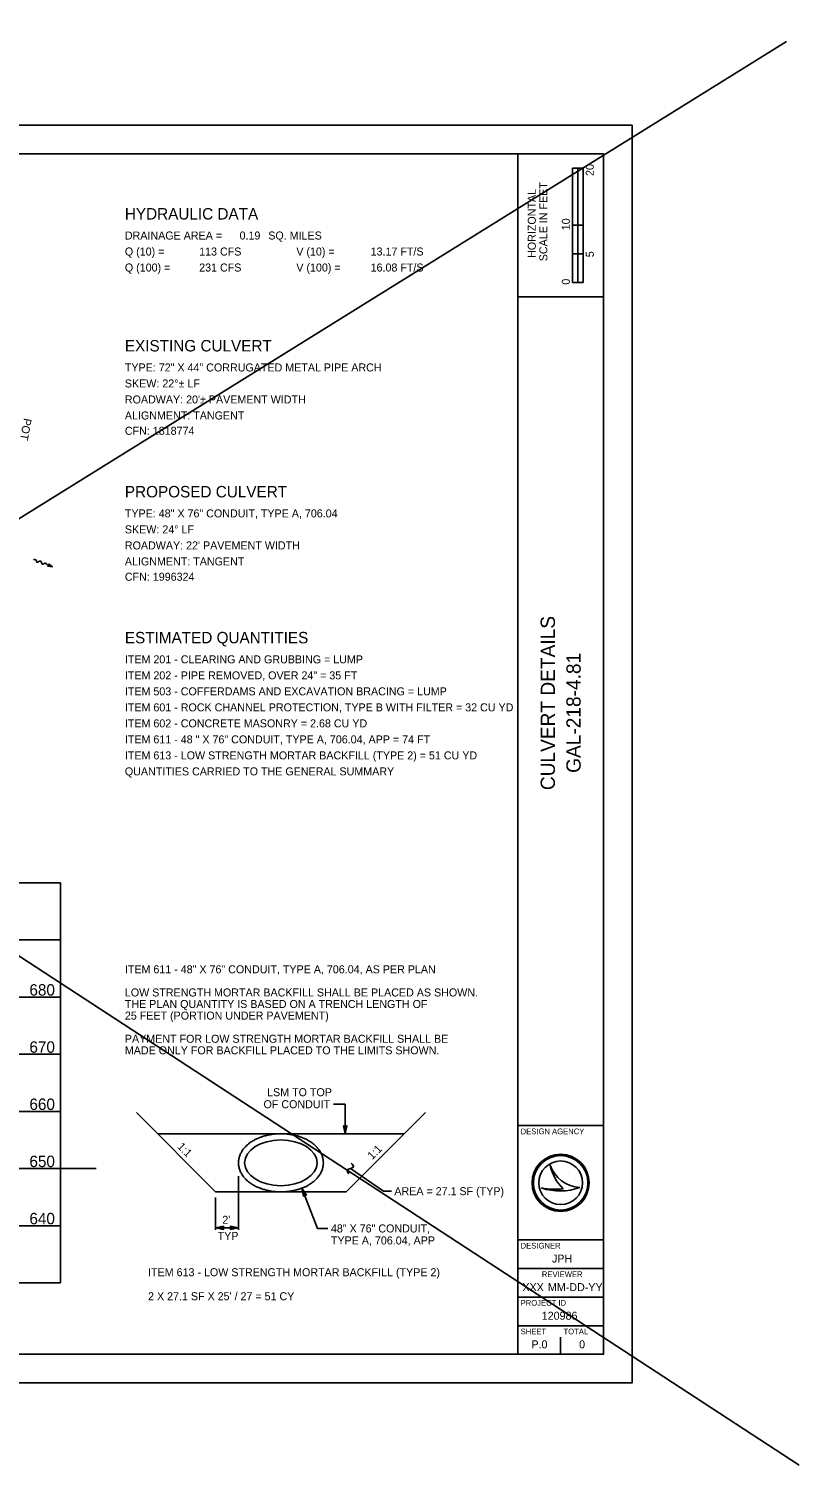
# Model space of a CAD drawing. Extents: x -1270 to 3371, y -118 to 220.
# Drawn here: x -1010.8 to -876, y -117.6 to 133.7 of the extents above; entities that cross this region are included whole.
import ezdxf

# ---------------------------------------------------------------- set-up
doc = ezdxf.new("R2010")
doc.units = 0
for name, color, linetype in [('_CIVIL_CONSTRUCTION', 7, 'Continuous'), ('Default', 7, 'Continuous'), ('DR_P_Culvert', 7, 'Continuous'), ('DR_X_Culvert', 7, 'Continuous'), ('GE_P_Alignment', 7, 'Continuous'), ('GE_P_Alignment_100_Distances', 7, 'Continuous'), ('PF_P_Grade_Line', 7, 'Continuous'), ('PF_X_Ground_Line', 7, 'Continuous'), ('SC_Scratch1', 7, 'Continuous'), ('TX_P_1', 7, 'Continuous'), ('TX_X_1', 7, 'Continuous')]:
    doc.layers.add(name, color=color, linetype=linetype)

msp = doc.modelspace()

# ---------------------------------------------------------------- linework, layer by layer
at = {"layer": '_CIVIL_CONSTRUCTION'}
for points in [[(-955.76, -58.24), (-955.2, -58.24), (-955.48, -59.64)], [(-962.25, -70.35), (-962.77, -70.55), (-963.02, -69.14)], [(-976.73, -75.81), (-976.73, -76.37), (-978.13, -76.09)], [(-975.53, -76.37), (-975.53, -75.81), (-974.13, -76.09)]]:
    msp.add_lwpolyline(points, close=True, dxfattribs=at)
at = {"layer": 'Default'}
msp.add_line((-1215.28, -65.72), (-999.03, -65.72), dxfattribs=at)
at = {"layer": 'DR_X_Culvert'}
msp.add_lwpolyline([(-1245.26, -103.22), (-905.26, -103.22), (-905.26, 116.78), (-1245.26, 116.78)], close=True, dxfattribs=at)
at = {"layer": 'GE_P_Alignment_100_Distances'}
for p, q in [((-1007.53, 39.64), (-1006.7, 39.55)), ((-1006.7, 39.55), (-1007.38, 40.04))]:
    msp.add_line(p, q, dxfattribs=at)
msp.add_spline([(-1006.7, 39.55), (-1007.48, 39.85), (-1007.76, 40.04), (-1007.93, 40.18), (-1008.46, 39.99), (-1008.76, 40.55), (-1009.43, 40.36), (-1009.46, 40.61), (-1009.97, 40.8)], degree=3, dxfattribs=at)
at = {"layer": 'PF_P_Grade_Line'}
for p, q in [((-978.13, -69.8), (-991.99, -55.94)), ((-955.28, -69.8), (-941.42, -55.94)), ((-945.12, -59.64), (-988.3, -59.64)), ((-955.28, -69.8), (-978.13, -69.8))]:
    msp.add_line(p, q, dxfattribs=at)
msp.add_ellipse((-966.71, -64.72), major_axis=(6.34, 0), ratio=0.630915, dxfattribs=at)
msp.add_open_spline([(-959.28, -64.72), (-959.28, -64.53), (-959.3, -64.34), (-959.36, -63.97), (-959.4, -63.79), (-959.51, -63.43), (-959.58, -63.25), (-959.75, -62.92), (-959.84, -62.75), (-960.05, -62.43), (-960.16, -62.28), (-960.41, -61.99), (-960.54, -61.85), (-960.97, -61.44), (-961.29, -61.2), (-962, -60.75), (-962.37, -60.56), (-963.16, -60.23), (-963.58, -60.09), (-964.43, -59.86), (-964.88, -59.78), (-965.78, -59.66), (-966.24, -59.64), (-967.17, -59.64), (-967.63, -59.66), (-968.54, -59.78), (-968.98, -59.86), (-969.84, -60.09), (-970.25, -60.23), (-971.04, -60.56), (-971.42, -60.75), (-972.12, -61.2), (-972.44, -61.44), (-972.87, -61.85), (-973, -61.99), (-973.25, -62.28), (-973.37, -62.43), (-973.57, -62.75), (-973.67, -62.92), (-973.83, -63.25), (-973.9, -63.43), (-974.01, -63.79), (-974.06, -63.97), (-974.12, -64.34), (-974.13, -64.53), (-974.13, -64.91), (-974.12, -65.1), (-974.06, -65.47), (-974.01, -65.65), (-973.9, -66.01), (-973.83, -66.18), (-973.67, -66.52), (-973.57, -66.69), (-973.37, -67), (-973.25, -67.15), (-973, -67.45), (-972.87, -67.59), (-972.44, -67.99), (-972.12, -68.24), (-971.42, -68.69), (-971.04, -68.88), (-970.25, -69.21), (-969.84, -69.35), (-968.98, -69.57), (-968.54, -69.66), (-967.63, -69.77), (-967.17, -69.8), (-966.24, -69.8), (-965.78, -69.77), (-964.88, -69.66), (-964.43, -69.57), (-963.58, -69.35), (-963.16, -69.21), (-962.37, -68.88), (-962, -68.69), (-961.29, -68.24), (-960.97, -67.99), (-960.54, -67.59), (-960.41, -67.45), (-960.16, -67.15), (-960.05, -67), (-959.84, -66.69), (-959.75, -66.52), (-959.58, -66.18), (-959.51, -66.01), (-959.4, -65.65), (-959.36, -65.47), (-959.3, -65.1), (-959.28, -64.91), (-959.28, -64.72)], degree=3, dxfattribs=at)
at = {"layer": 'PF_X_Ground_Line'}
for p, q in [((-1225.28, -25.72), (-1005.28, -25.72)), ((-1225.28, -35.72), (-1005.28, -35.72)), ((-1225.28, -45.72), (-1005.28, -45.72)), ((-1225.28, -55.72), (-1005.28, -55.72)), ((-1225.28, -65.72), (-1005.28, -65.72)), ((-1225.28, -75.72), (-1005.28, -75.72))]:
    msp.add_line(p, q, dxfattribs=at)
at = {"layer": 'SC_Scratch1'}
for p, q in [((-915.7, 89.28), (-915.7, 109.28)), ((-913.82, 109.28), (-915.7, 109.28)), ((-915.7, 99.28), (-915.7, 109.28)), ((-915.7, 109.28), (-914.76, 109.28)), ((-914.76, 109.28), (-914.76, 99.28)), ((-914.76, 109.28), (-914.76, 109.28)), ((-913.82, 109.28), (-913.82, 89.28)), ((-914.76, 99.28), (-915.7, 99.28)), ((-913.83, 99.28), (-914.76, 99.28)), ((-914.76, 99.28), (-914.76, 94.28)), ((-913.83, 94.28), (-913.83, 99.28)), ((-914.76, 94.28), (-915.7, 94.28)), ((-915.7, 94.28), (-915.7, 89.28)), ((-914.76, 89.28), (-914.76, 94.28)), ((-914.76, 94.28), (-913.83, 94.28)), ((-913.82, 89.28), (-915.7, 89.28)), ((-915.7, 89.28), (-914.76, 89.28)), ((-1005.28, -15.72), (-1225.28, -15.72)), ((-1005.28, -85.72), (-1005.28, -15.72)), ((-919.59, -65.12), (-919.59, -65.12)), ((-921.09, -69.12), (-921.09, -69.12)), ((-917.76, -68.22), (-917.76, -68.22)), ((-914.39, -69.03), (-914.39, -69.03)), ((-1225.28, -85.72), (-1005.28, -85.72)), ((-917.76, -98.22), (-917.76, -95.22)), ((-921.51, -96.47), (-921.51, -96.47))]:
    msp.add_line(p, q, dxfattribs=at)
for radius in [5, 4.77, 4.77, 3.82]:
    msp.add_circle((-917.76, -68.22), radius, dxfattribs=at)
for centre, radius, start, end in [((-914.1, -63.24), 5.8, 198.9257, 198.9319), ((-911.8, -63.52), 7.96, 191.6379, 191.6421), ((-914.1, -63.24), 5.8, 198.9319, 267.1657), ((-911.8, -63.52), 7.96, 191.6421, 226.0947), ((-917.87, -59.52), 10.13, 251.4576, 290.0832), ((-918.78, -56.68), 12.66, 259.4964, 259.4995), ((-917.87, -59.52), 10.13, 251.4527, 251.4576), ((-918.78, -56.68), 12.66, 259.4995, 276.6672)]:
    msp.add_arc(centre, radius, start, end, dxfattribs=at)
at = {"layer": 'TX_P_1'}
for p, q in [((-1261.12, 133.66), (-876.01, -117.63)), ((-878.22, 131.45), (-1269.59, -111.73)), ((-955.48, -54.47), (-957.53, -54.47)), ((-955.48, -59.64), (-955.48, -54.47)), ((-974.13, -67.05), (-974.13, -76.45)), ((-948.77, -69.68), (-954.55, -65.69)), ((-963.02, -69.14), (-960.3, -76.2)), ((-947.37, -69.68), (-948.77, -69.68)), ((-978.13, -70.78), (-978.13, -76.45)), ((-978.13, -76.09), (-974.13, -76.09)), ((-960.3, -76.2), (-958.49, -76.2))]:
    msp.add_line(p, q, dxfattribs=at)
msp.add_spline([(-954.83, -66.66), (-955.1, -65.97), (-954.03, -65.43), (-954.42, -64.78)], degree=3, dxfattribs=at)
at = {"layer": 'TX_X_1'}
for p, q in [((-925.26, -98.22), (-925.26, 111.78)), ((-925.26, 86.78), (-910.26, 86.78)), ((-925.26, -58.22), (-910.26, -58.22)), ((-925.26, -78.22), (-910.26, -78.22)), ((-925.26, -83.22), (-910.26, -83.22)), ((-925.26, -88.22), (-910.26, -88.22)), ((-925.26, -93.22), (-910.26, -93.22))]:
    msp.add_line(p, q, dxfattribs=at)
msp.add_lwpolyline([(-1230.26, 111.78), (-910.26, 111.78), (-910.26, -98.22), (-1230.26, -98.22)], close=True, dxfattribs=at)

# ---------------------------------------------------------------- texts
at = {"layer": 'DR_P_Culvert'}
msp.add_text('POT', height=1.4, rotation=259.759, dxfattribs=at).set_placement((-1011.69, 65.6))
at = {"layer": 'GE_P_Alignment'}
for s, p in [('ITEM 611 - 48" X 76" CONDUIT, TYPE A, 706.04, AS PER PLAN', (-994.01, -31.57)), ('LOW STRENGTH MORTAR BACKFILL SHALL BE PLACED AS SHOWN.', (-994.01, -35.62)), ('THE PLAN QUANTITY IS BASED ON A TRENCH LENGTH OF ', (-994.01, -37.64)), ('25 FEET (PORTION UNDER PAVEMENT)', (-994.01, -39.67)), ('PAYMENT FOR LOW STRENGTH MORTAR BACKFILL SHALL BE', (-994.01, -43.72)), ('MADE ONLY FOR BACKFILL PLACED TO THE LIMITS SHOWN.', (-994.01, -45.74))]:
    msp.add_text(s, height=1.4, dxfattribs=at).set_placement(p)
at = {"layer": 'SC_Scratch1'}
for s, height, p in [('20', 1.4, (-911.96, 107.91)), ('HORIZONTAL', 1.4, (-922.11, 93.57)), ('SCALE IN FEET', 1.4, (-920.09, 92.99)), ('10', 1.4, (-916.16, 98.41)), ('5', 1.4, (-911.96, 93.69)), ('0', 1.4, (-916.16, 88.89)), ('CULVERT DETAILS', 2.5, (-918.76, 0.47)), ('GAL-218-4.81', 2.5, (-914.26, 3.49))]:
    msp.add_text(s, height=height, rotation=90, dxfattribs=at).set_placement(p)
for s, height, p in [('HYDRAULIC DATA', 2, (-994.01, 100.29)), ('DRAINAGE AREA =', 1.4, (-994.01, 96.79)), ('0.19', 1.4, (-973.94, 96.79)), ('SQ. MILES', 1.4, (-968.92, 96.79)), ('Q (10) =', 1.4, (-994.01, 93.99)), ('113 CFS', 1.4, (-981.01, 93.99)), ('V (10) =', 1.4, (-964.01, 93.99)), ('13.17 FT/S', 1.4, (-951.01, 93.99)), ('Q (100) =', 1.4, (-994.01, 91.19)), ('231 CFS', 1.4, (-981.01, 91.19)), ('V (100) =', 1.4, (-964.01, 91.19)), ('16.08 FT/S', 1.4, (-951.01, 91.19)), ('EXISTING CULVERT', 2, (-994.01, 77.21)), ('TYPE: 72" X 44" CORRUGATED METAL PIPE ARCH', 1.4, (-994.01, 73.71)), ('SKEW: 22°± LF', 1.4, (-994.01, 70.91)), ("ROADWAY: 20'± PAVEMENT WIDTH", 1.4, (-994.01, 68.11)), ('ALIGNMENT: TANGENT', 1.4, (-994.01, 65.31)), ('CFN: 1818774', 1.4, (-994.01, 62.63)), ('PROPOSED CULVERT', 2, (-994.01, 51.68)), ('TYPE: 48" X 76" CONDUIT, TYPE A, 706.04', 1.4, (-994.01, 48.18)), ('SKEW: 24° LF', 1.4, (-994.01, 45.38)), ("ROADWAY: 22' PAVEMENT WIDTH", 1.4, (-994.01, 42.58)), ('ALIGNMENT: TANGENT', 1.4, (-994.01, 39.78)), ('CFN: 1996324', 1.4, (-994.01, 37.1)), ('ESTIMATED QUANTITIES', 2, (-994.01, 26.15)), ('ITEM 201 - CLEARING AND GRUBBING = LUMP', 1.4, (-994.01, 22.65)), ('ITEM 202 - PIPE REMOVED, OVER 24" = 35 FT', 1.4, (-994.01, 19.85)), ('ITEM 503 - COFFERDAMS AND EXCAVATION BRACING = LUMP', 1.4, (-994.01, 17.05)), ('ITEM 601 - ROCK CHANNEL PROTECTION, TYPE B WITH FILTER = 32 CU YD', 1.4, (-994.01, 14.25)), ('ITEM 602 - CONCRETE MASONRY = 2.68 CU YD', 1.4, (-994.01, 11.45)), ('ITEM 611 - 48 " X 76" CONDUIT, TYPE A, 706.04, APP = 74 FT', 1.4, (-994.01, 8.65)), ('ITEM 613 - LOW STRENGTH MORTAR BACKFILL (TYPE 2) = 51 CU YD', 1.4, (-994.01, 5.85)), ('QUANTITIES CARRIED TO THE GENERAL SUMMARY', 1.4, (-994.01, 3.05)), ('680', 2, (-1010.71, -35.47)), ('670', 2, (-1010.71, -45.47)), ('660', 2, (-1010.71, -55.47)), ('DESIGN AGENCY', 1, (-924.76, -59.72)), ('650', 2, (-1010.71, -65.47)), ('640', 2, (-1010.71, -75.47)), ('DESIGNER', 1, (-924.76, -79.72)), ('JPH', 1.4, (-919.28, -82.17)), ('REVIEWER', 1, (-921.05, -84.72)), ('XXX', 1.4, (-924.45, -87.17)), ('MM-DD-YY', 1.4, (-919.99, -87.17)), ('PROJECT ID', 1, (-924.76, -89.72)), ('120986', 1.4, (-921.07, -92.17)), ('SHEET', 1, (-924.76, -94.72)), ('TOTAL', 1, (-917.26, -94.72)), ('P.0', 1.4, (-922.88, -97.17)), ('0', 1.4, (-914.53, -97.17))]:
    msp.add_text(s, height=height, dxfattribs=at).set_placement(p)
at = {"layer": 'TX_P_1'}
for s, p in [('LSM TO TOP', (-969.12, -53.07)), ('OF CONDUIT', (-969.75, -55.17)), ('AREA = 27.1 SF (TYP)', (-946.86, -70.38)), ("2'", (-976.96, -75.39)), ('TYP', (-977.78, -78.21)), ('48" X 76" CONDUIT,', (-957.96, -76.9)), ('TYPE A, 706.04, APP', (-957.96, -79)), ('ITEM 613 - LOW STRENGTH MORTAR BACKFILL (TYPE 2)', (-989.95, -84.56)), ("2 X 27.1 SF X 25' / 27 = 51 CY", (-989.95, -88.76))]:
    msp.add_text(s, height=1.4, dxfattribs=at).set_placement(p)
for rotation, p in [(315, (-984.93, -62.01)), (45, (-950.74, -64.26))]:
    msp.add_text('1:1', height=1.4, rotation=rotation, dxfattribs=at).set_placement(p)

doc.saveas('drawing.dxf')
